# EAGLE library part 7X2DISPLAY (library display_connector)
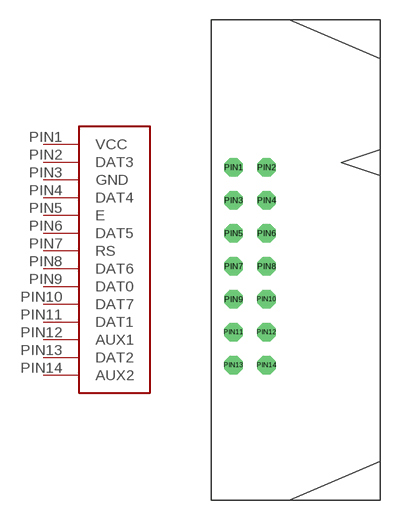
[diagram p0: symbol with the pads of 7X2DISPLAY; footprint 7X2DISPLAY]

Designator prefix -

## 7X2DISPLAY  [7X2DISPLAY]
PIN1  VCC
PIN2  DAT3
PIN3  GND
PIN4  DAT4
PIN5  E
PIN6  DAT5
PIN7  RS
PIN8  DAT6
PIN9  DAT0
PIN10  DAT7
PIN11  DAT1
PIN12  AUX1
PIN13  DAT2
PIN14  AUX2

## Footprint 7X2DISPLAY (pad centres in mm)
drill 0.8 pad 1.422 octagon: PIN1 -1.27,7.62; PIN2 1.27,7.62; PIN3 -1.27,5.08; PIN4 1.27,5.08; PIN5 -1.27,2.54; PIN6 1.27,2.54; PIN7 -1.27,0; PIN8 1.27,0; PIN9 -1.27,-2.54; PIN10 1.27,-2.54; PIN11 -1.27,-5.08; PIN12 1.27,-5.08; PIN13 -1.27,-7.62; PIN14 1.27,-7.62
